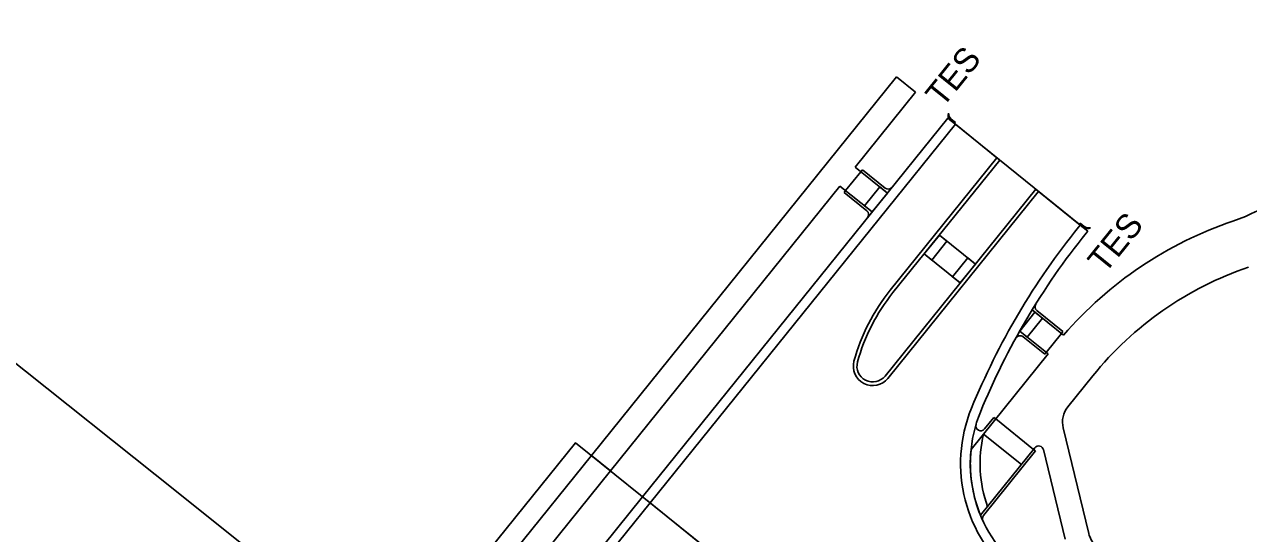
# Model space of a CAD drawing. Extents: x 1487693 to 1489338, y 497936 to 499734.
# Drawn here: x 1488696.3 to 1488948.1, y 499246.2 to 499350.8 of the extents above; entities that cross this region are included whole.
import ezdxf

# ---------------------------------------------------------------- set-up
doc = ezdxf.new("R2010")
doc.units = 0
for name, color, linetype in [('Exist Railroads Standard Gauge', 7, 'Continuous'), ('Pattern 5', 7, 'Continuous'), ('Prop Conc 1ft 6in Curb and Gutter', 7, 'Continuous'), ('Prop Conc 2ft 6in Curb and Gutter', 7, 'Continuous'), ('Prop Conc 4in Sidewalk', 7, 'Continuous'), ('Prop EOT', 7, 'Continuous'), ('Prop Guardrail', 7, 'Continuous'), ('Prop Guardrail Anchor Unit CELL', 7, 'Continuous'), ('Scratch_Level_5', 7, 'Continuous')]:
    doc.layers.add(name, color=color, linetype=linetype)

msp = doc.modelspace()

# ---------------------------------------------------------------- linework, layer by layer
at = {"layer": 'Exist Railroads Standard Gauge'}
msp.add_lwpolyline([(1488972.75, 499057.15), (1488947.35, 499077.62), (1488919.48, 499100.08), (1488890.07, 499123.82), (1488841.68, 499162.79), (1488822.88, 499177.94), (1488795.51, 499200.11), (1488763.62, 499225.91), (1488727.57, 499254.8), (1488692.17, 499283.06), (1488664.12, 499305.6), (1488617.82, 499342.84), (1488599.16, 499357.84), (1488532.76, 499411.39), (1488485.03, 499449.93), (1488450.03, 499478.08), (1488423.37, 499499.63), (1488397.39, 499520.51), (1488361.21, 499549.74)], dxfattribs=at)
at = {"layer": 'Pattern 5'}
for p, q in [((1488872.25, 499317.42), (1488869.11, 499313.53)), ((1488870.66, 499312.27), (1488873.8, 499316.17)), ((1488873.8, 499316.17), (1488872.25, 499317.42)), ((1488869.11, 499313.53), (1488870.66, 499312.27)), ((1488884.5, 499307.53), (1488881.37, 499303.64)), ((1488882.92, 499302.38), (1488886.06, 499306.28)), ((1488886.06, 499306.28), (1488884.5, 499307.53)), ((1488881.37, 499303.64), (1488882.92, 499302.38)), ((1488890.34, 499302.82), (1488887.2, 499298.93)), ((1488891.9, 499301.57), (1488890.34, 499302.82)), ((1488888.76, 499297.68), (1488891.9, 499301.57)), ((1488887.2, 499298.93), (1488888.76, 499297.68)), ((1488904.16, 499291.68), (1488901.02, 499287.79)), ((1488902.58, 499286.53), (1488905.72, 499290.43)), ((1488905.72, 499290.43), (1488904.16, 499291.68)), ((1488901.02, 499287.79), (1488902.58, 499286.53)), ((1488893.58, 499266.61), (1488891.01, 499263.42)), ((1488892.95, 499249.9), (1488894.4, 499251.7))]:
    msp.add_line(p, q, dxfattribs=at)
for radius, start, end in [(26, 166.4473, 199.835), (28, 174.0509, 202.2902)]:
    msp.add_arc((1488918.86, 499260.52), radius, start, end, dxfattribs=at)
at = {"layer": 'Prop Conc 1ft 6in Curb and Gutter'}
for p, q in [((1488874.95, 499295.69), (1488896.93, 499322.93)), ((1488896.93, 499322.93), (1488896.34, 499323.4)), ((1488868.35, 499320.56), (1488868.67, 499320.95)), ((1488868.67, 499320.95), (1488873.34, 499317.18)), ((1488865.21, 499316.67), (1488864.9, 499316.28)), ((1488864.9, 499316.28), (1488869.57, 499312.51)), ((1488873.32, 499278.53), (1488904.32, 499316.97)), ((1488904.9, 499316.5), (1488904.32, 499316.97)), ((1488909.92, 499287.68), (1488904.53, 499292.03)), ((1488909.61, 499287.29), (1488909.92, 499287.68)), ((1488906.16, 499283.01), (1488901.7, 499286.6)), ((1488906.47, 499283.39), (1488906.16, 499283.01)), ((1488893.77, 499267.65), (1488895.7, 499270.04)), ((1488896.09, 499269.73), (1488895.7, 499270.04)), ((1488893.55, 499249.86), (1488904.26, 499263.14)), ((1488903.88, 499263.45), (1488904.26, 499263.14))]:
    msp.add_line(p, q, dxfattribs=at)
for centre, radius, start, end in [((1488873.97, 499317.96), 1, 231.1327, 321.1156), ((1488868.94, 499311.73), 1, 321.1156, 51.1156), ((1488905.51, 499271.05), 39.25, 141.1156, 164.6721), ((1488905.16, 499292.8), 1, 148.0494, 231.1156), ((1488901.07, 499285.82), 1, 51.1156, 151.2037), ((1488870.79, 499280.57), 3.25, 164.6721, 321.1156), ((1488892.99, 499268.28), 1, 163.3073, 321.1156), ((1488894.33, 499249.23), 1, 141.1156, 204.7278)]:
    msp.add_arc(centre, radius, start, end, dxfattribs=at)
at = {"layer": 'Prop Conc 2ft 6in Curb and Gutter'}
for p, q in [((1488823.45, 499253.72), (1488886.22, 499331.56)), ((1488886.22, 499331.56), (1488887.78, 499330.31)), ((1488915.02, 499308.34), (1488913.47, 499309.59)), ((1488914.69, 499307.92), (1488915.02, 499308.34)), ((1488794.57, 499217.92), (1488823.44, 499253.71)), ((1488825, 499252.47), (1488823.45, 499253.72)), ((1488825, 499252.47), (1488823.45, 499253.72))]:
    msp.add_line(p, q, dxfattribs=at)
for centre, radius, start, end in [((1489029.89, 499215.01), 148, 141.1156, 157.7135), ((1488918.86, 499260.52), 28, 157.7135, 231.1156)]:
    msp.add_arc(centre, radius, start, end, dxfattribs=at)
at = {"layer": 'Prop Conc 4in Sidewalk'}
for p, q in [((1488812.94, 499262.2), (1488875.71, 499340.04)), ((1488875.71, 499340.04), (1488879.61, 499336.9)), ((1488867.19, 499321.5), (1488879.61, 499336.9)), ((1488865.21, 499316.67), (1488868.35, 499320.56)), ((1488867.19, 499321.5), (1488873.8, 499316.17)), ((1488816.83, 499259.06), (1488864.05, 499317.61)), ((1488864.05, 499317.61), (1488870.66, 499312.27)), ((1488869.11, 499313.53), (1488872.25, 499317.42)), ((1488870.66, 499312.27), (1488873.8, 499316.17)), ((1488881.37, 499303.64), (1488884.5, 499307.53)), ((1488882.92, 499302.38), (1488886.06, 499306.28)), ((1488884.5, 499307.53), (1488891.9, 499301.57)), ((1488881.37, 499303.64), (1488888.76, 499297.68)), ((1488887.2, 499298.93), (1488890.34, 499302.82)), ((1488888.76, 499297.68), (1488891.9, 499301.57)), ((1488901.02, 499287.79), (1488904.16, 499291.68)), ((1488902.58, 499286.53), (1488905.72, 499290.43)), ((1488910, 499286.97), (1488903.58, 499292.15)), ((1488906.86, 499283.08), (1488901.02, 499287.79)), ((1488906.47, 499283.39), (1488909.61, 499287.29)), ((1488910, 499286.97), (1488910.04, 499286.95)), ((1488891.01, 499263.42), (1488906.86, 499283.08)), ((1488910.92, 499272.19), (1488916.06, 499278.56)), ((1488896.09, 499269.73), (1488903.88, 499263.45)), ((1488915.22, 499246.16), (1488909.96, 499267.88)), ((1488893.58, 499266.61), (1488901.36, 499260.34)), ((1488892.95, 499249.9), (1488904.15, 499263.79)), ((1488910.36, 499244.98), (1488905.9, 499263.4)), ((1488797.24, 499242.74), (1488812.93, 499262.19)), ((1488812.94, 499262.2), (1488816.83, 499259.06)), ((1488812.94, 499262.2), (1488816.83, 499259.06)), ((1488801.14, 499239.6), (1488816.82, 499259.05))]:
    msp.add_line(p, q, dxfattribs=at)
for centre, radius, start, end in [((1488933.64, 499343.53), 35, 288.7222, 358.8847), ((1488970.55, 499234.62), 80, 108.7222, 139.1474), ((1488970.55, 499234.62), 70, 108.7222, 141.1156), ((1488914.82, 499269.05), 5, 141.1156, 193.6145), ((1488918.86, 499260.52), 26, 166.4473, 199.835), ((1488904.93, 499263.16), 1, 13.6145, 141.1156), ((1488920.08, 499247.33), 5, 193.6145, 231.1156)]:
    msp.add_arc(centre, radius, start, end, dxfattribs=at)
at = {"layer": 'Prop EOT'}
for p, q in [((1488825, 499252.47), (1488887.78, 499330.31)), ((1488887.78, 499330.31), (1488896.34, 499323.4)), ((1488874.37, 499296.16), (1488896.34, 499323.4)), ((1488873.9, 499278.05), (1488904.83, 499316.4)), ((1488904.83, 499316.4), (1488904.9, 499316.5)), ((1488904.9, 499316.5), (1488913.47, 499309.59)), ((1488913.13, 499309.18), (1488913.47, 499309.59)), ((1488743.39, 499151.27), (1488825, 499252.46)), ((1488865.2, 499220.05), (1488825, 499252.47)), ((1488865.2, 499220.05), (1488825, 499252.47))]:
    msp.add_line(p, q, dxfattribs=at)
for centre, radius, start, end in [((1489029.89, 499215.01), 150, 141.1156, 157.7135), ((1488905.51, 499271.05), 40, 141.1156, 164.6721), ((1488870.79, 499280.57), 4, 164.6721, 321.1156), ((1488918.86, 499260.52), 30, 157.7135, 231.1156)]:
    msp.add_arc(centre, radius, start, end, dxfattribs=at)
at = {"layer": 'Prop Guardrail'}
msp.add_line((1488913.24, 499309.78), (1488887.62, 499330.44), dxfattribs=at)
at = {"layer": 'Prop Guardrail Anchor Unit CELL'}
for p, q in [((1488887.62, 499330.44), (1488886.74, 499331.15)), ((1488887.79, 499330.66), (1488886.92, 499331.37)), ((1488887.62, 499330.44), (1488887.79, 499330.66)), ((1488913.24, 499309.78), (1488913.42, 499310)), ((1488913.24, 499309.78), (1488914.12, 499309.07)), ((1488913.42, 499310), (1488914.29, 499309.29))]:
    msp.add_line(p, q, dxfattribs=at)
for centre, radius, start, end in [((1488887.56, 499332.11), 1.27, 159.0507, 229.4447), ((1488887.98, 499332.56), 1.6, 179.9907, 228.2982), ((1488914.88, 499310.08), 1.27, 232.7866, 303.1806), ((1488915.23, 499310.58), 1.6, 233.9331, 282.2406)]:
    msp.add_arc(centre, radius, start, end, dxfattribs=at)
at = {"layer": 'Scratch_Level_5'}
msp.add_lwpolyline([(1488728.07, 499163.61), (1488809.66, 499264.82), (1488874.01, 499212.95), (1488792.43, 499111.74)], close=True, dxfattribs=at)

# ---------------------------------------------------------------- texts
at = {"layer": 'Prop Guardrail Anchor Unit CELL'}
for p in [(1488885.17, 499333.55), (1488918.54, 499299.4)]:
    msp.add_text('TES', height=5, rotation=51.1156, dxfattribs=at).set_placement(p)

doc.saveas('drawing.dxf')
